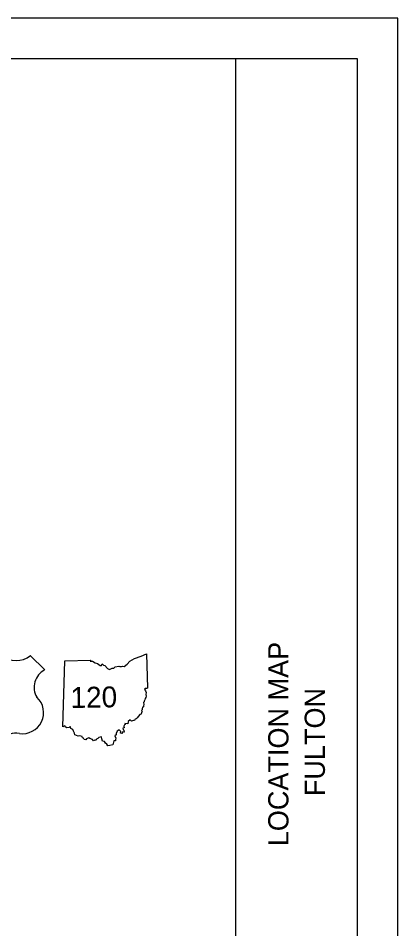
# Model space of a CAD drawing. Extents: x 0 to 849, y 0 to 440.
# Drawn here: x 586.2 to 680, y 214.9 to 440 of the extents above; entities that cross this region are included whole.
import ezdxf

# ---------------------------------------------------------------- set-up
doc = ezdxf.new("R2010")
doc.units = 0
for name, color, linetype in [('PV_P_Walk', 7, 'Continuous'), ('SH_Border', 7, 'Continuous'), ('SH_Cut_Line', 7, 'Continuous'), ('SH_Data', 7, 'Continuous')]:
    doc.layers.add(name, color=color, linetype=linetype)

msp = doc.modelspace()

# ---------------------------------------------------------------- linework, layer by layer
at = {"layer": 'PV_P_Walk'}
for p, q in [((592.78, 278.86), (589.23, 282.41)), ((597.3, 264.78), (597.76, 281.15))]:
    msp.add_line(p, q, dxfattribs=at)
for points in [[(597.76, 281.15), (604.11, 281.26), (604.01, 281.06), (604.61, 281.02), (605.25, 280.67), (605.79, 280.45), (606.45, 279.93), (606.84, 279.93), (607.01, 280.36), (607.31, 280.03), (607.67, 279.97), (608.29, 279.19), (608.8, 279.02), (609.41, 279.29), (609.87, 279.33), (610.2, 279.6), (611.07, 279.82), (611.32, 279.69), (611.78, 279.71), (612.01, 279.82), (612.41, 279.73), (613.12, 280.32), (613.85, 281.02), (614.97, 281.69), (616.65, 282.31), (617.97, 282.87), (618.17, 274.38)], [(618.17, 274.38), (617.97, 274.26), (617.67, 274.31), (617.46, 274.08), (617.71, 273.68), (617.83, 273.26), (617.73, 272.79), (617.83, 272.41), (617.76, 272.09), (617.57, 271.78), (617.5, 271.47), (617.34, 271.15), (617.35, 270.97), (617.2, 270.83), (617.23, 270.3), (617.15, 270.01), (617.18, 269.75), (616.92, 269.69), (616.98, 269.48), (616.82, 269.31), (616.86, 269.03), (616.68, 268.86), (616.85, 268.5), (616.71, 268.39), (616.59, 267.95), (616.27, 267.87), (615.62, 267.07), (615.4, 266.77), (615.14, 266.7), (615, 266.39), (614.68, 266.39), (614.21, 266.18), (613.9, 266.54), (613.36, 266.1), (613.29, 265.59), (612.61, 265.61), (612.64, 265.35), (612.49, 265.27), (612.35, 265.01), (612.43, 264.56), (612.11, 264.44), (612.15, 264.17), (612.35, 264.01), (612.44, 263.5), (612.1, 263.6), (611.82, 263.17), (611.54, 263.27), (611.63, 263.64), (611.15, 264.07), (610.69, 263.72), (610.45, 263.16), (610.45, 262.79), (610.11, 262.56), (610.33, 262.03), (610.29, 261.66), (610.29, 261.31), (609.87, 261.32), (609.61, 260.38)], [(609.61, 260.38), (608.87, 260.2), (608.35, 260.1), (608.17, 260.52), (607.8, 260.75), (607.56, 261.18), (607.03, 261.24), (606.91, 261.83), (606.85, 262.31), (606.13, 262.19), (605.93, 261.9), (605.67, 261.82), (605.52, 261.52), (605.17, 261.5), (604.8, 261.36), (604.55, 261.65), (603.94, 261.94), (603.66, 262.09), (603.09, 261.85), (602.96, 261.58), (602.5, 261.7), (602.4, 262.01), (602.12, 262.1), (602.06, 262.43), (601.46, 262.6), (601.01, 262.53), (600.21, 262.79), (600.16, 263.22), (599.88, 263.75), (599.74, 264.11), (599.23, 264.39), (599.13, 264.82), (598.97, 264.8), (598.82, 264.63), (598.26, 264.55), (598.03, 264.73), (597.72, 265.03), (597.3, 264.78)]]:
    msp.add_lwpolyline(points, dxfattribs=at)
for centre, radius, start, end in [((585.71, 286.89), 5.7, 231.813, 308.187), ((594.99, 274.58), 4.82, 117.3892, 210.8825), ((587.31, 268.31), 5.2, 261.2718, 46.9954), ((585.66, 258.31), 4.94, 79.9613, 134.7468), ((585.66, 258.31), 4.94, 79.9613, 134.7468)]:
    msp.add_arc(centre, radius, start, end, dxfattribs=at)
at = {"layer": 'SH_Border'}
msp.add_line((640, 10), (640, 430), dxfattribs=at)
msp.add_lwpolyline([(30, 430), (670, 430), (670, 10), (30, 10)], close=True, dxfattribs=at)
at = {"layer": 'SH_Cut_Line'}
msp.add_lwpolyline([(0, 0), (680, 0), (680, 440), (0, 440)], close=True, dxfattribs=at)

# ---------------------------------------------------------------- texts
at = {"layer": 'PV_P_Walk'}
msp.add_text('120', height=5.162, rotation=1.0142, dxfattribs=at).set_placement((599.21, 269.45))
at = {"layer": 'SH_Data'}
for s, p in [('LOCATION MAP', (653, 235.29)), ('FULTON', (662, 247.67))]:
    msp.add_text(s, height=5, rotation=90, dxfattribs=at).set_placement(p)

doc.saveas('drawing.dxf')
